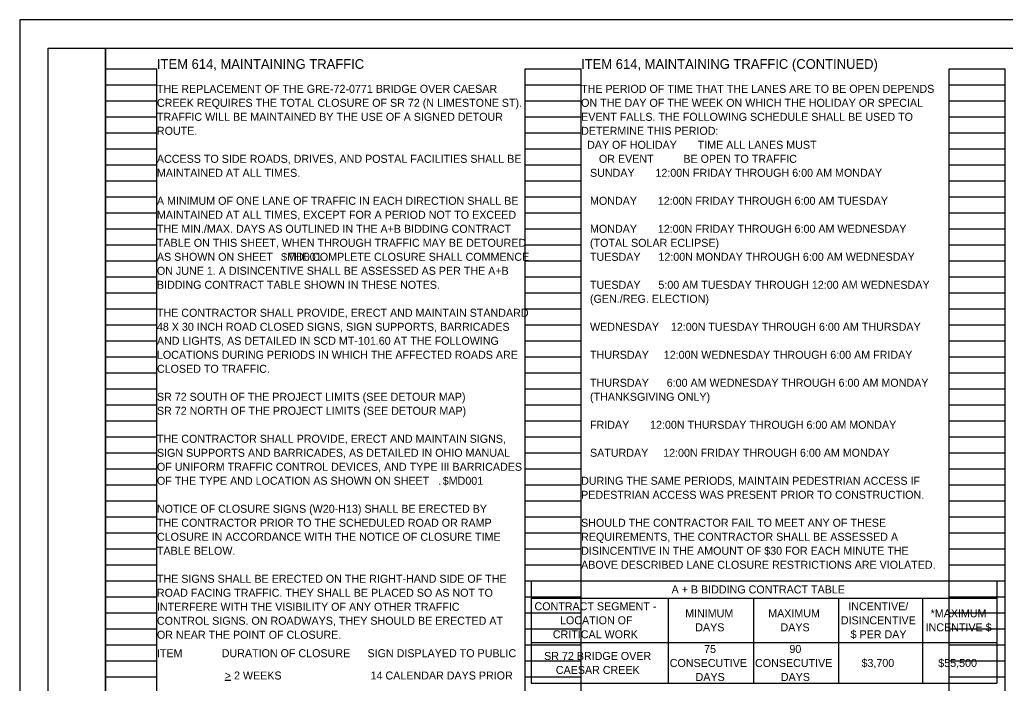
# Model space of a CAD drawing. Extents: x 0 to 69, y 0 to 22.
# Drawn here: x 0 to 17.24, y 10.39 to 22 of the extents above; entities that cross this region are included whole.
import ezdxf

# ---------------------------------------------------------------- set-up
doc = ezdxf.new("R2010")
doc.units = 0
for name, color, linetype in [('GM_X_City_Street', 7, 'Continuous'), ('GM_X_US_Route', 7, 'Continuous'), ('SH_Border', 7, 'Continuous'), ('SH_Cut_Line', 7, 'Continuous'), ('SH_Text', 7, 'Continuous')]:
    doc.layers.add(name, color=color, linetype=linetype)

msp = doc.modelspace()

# ---------------------------------------------------------------- linework, layer by layer
at = {"layer": 'GM_X_City_Street'}
for p, q in [((1.5, 0.98), (1.5, 21.14)), ((1.5, 21.14), (2.4, 21.14)), ((2.4, 0.98), (2.4, 21.14)), ((8.84, 0.98), (8.84, 21.14)), ((8.84, 21.14), (9.82, 21.14)), ((9.82, 0.98), (9.82, 21.14)), ((16.26, 0.98), (16.26, 21.14)), ((16.26, 21.14), (17.24, 21.14)), ((17.24, 0.98), (17.24, 21.14)), ((1.5, 20.86), (2.4, 20.86)), ((8.84, 20.86), (9.82, 20.86)), ((16.26, 20.86), (17.24, 20.86)), ((1.5, 20.58), (2.4, 20.58)), ((8.84, 20.58), (9.82, 20.58)), ((16.26, 20.58), (17.24, 20.58)), ((1.5, 20.3), (2.4, 20.3)), ((8.84, 20.3), (9.82, 20.3)), ((16.26, 20.3), (17.24, 20.3)), ((1.5, 20.02), (2.4, 20.02)), ((8.84, 20.02), (9.82, 20.02)), ((16.26, 20.02), (17.24, 20.02)), ((1.5, 19.74), (2.4, 19.74)), ((8.84, 19.74), (9.82, 19.74)), ((16.26, 19.74), (17.24, 19.74)), ((1.5, 19.46), (2.4, 19.46)), ((8.84, 19.46), (9.82, 19.46)), ((16.26, 19.46), (17.24, 19.46)), ((1.5, 19.18), (2.4, 19.18)), ((8.84, 19.18), (9.82, 19.18)), ((16.26, 19.18), (17.24, 19.18)), ((1.5, 18.9), (2.4, 18.9)), ((8.84, 18.9), (9.82, 18.9)), ((16.26, 18.9), (17.24, 18.9)), ((1.5, 18.62), (2.4, 18.62)), ((8.84, 18.62), (9.82, 18.62)), ((16.26, 18.62), (17.24, 18.62)), ((1.5, 18.34), (2.4, 18.34)), ((8.84, 18.34), (9.82, 18.34)), ((16.26, 18.34), (17.24, 18.34)), ((1.5, 18.06), (2.4, 18.06)), ((8.84, 18.06), (9.82, 18.06)), ((16.26, 18.06), (17.24, 18.06)), ((1.5, 17.78), (2.4, 17.78)), ((8.84, 17.78), (9.82, 17.78)), ((16.26, 17.78), (17.24, 17.78)), ((1.5, 17.5), (2.4, 17.5)), ((8.84, 17.5), (9.82, 17.5)), ((16.26, 17.5), (17.24, 17.5)), ((1.5, 17.22), (2.4, 17.22)), ((8.84, 17.22), (9.82, 17.22)), ((16.26, 17.22), (17.24, 17.22)), ((1.5, 16.94), (2.4, 16.94)), ((8.84, 16.94), (9.82, 16.94)), ((16.26, 16.94), (17.24, 16.94)), ((1.5, 16.66), (2.4, 16.66)), ((8.84, 16.66), (9.82, 16.66)), ((16.26, 16.66), (17.24, 16.66)), ((1.5, 16.38), (2.4, 16.38)), ((8.84, 16.38), (9.82, 16.38)), ((16.26, 16.38), (17.24, 16.38)), ((1.5, 16.1), (2.4, 16.1)), ((8.84, 16.1), (9.82, 16.1)), ((16.26, 16.1), (17.24, 16.1)), ((1.5, 15.82), (2.4, 15.82)), ((8.84, 15.82), (9.82, 15.82)), ((16.26, 15.82), (17.24, 15.82)), ((1.5, 15.54), (2.4, 15.54)), ((8.84, 15.54), (9.82, 15.54)), ((16.26, 15.54), (17.24, 15.54)), ((1.5, 15.26), (2.4, 15.26)), ((8.84, 15.26), (9.82, 15.26)), ((16.26, 15.26), (17.24, 15.26)), ((1.5, 14.98), (2.4, 14.98)), ((8.84, 14.98), (9.82, 14.98)), ((16.26, 14.98), (17.24, 14.98)), ((1.5, 14.7), (2.4, 14.7)), ((8.84, 14.7), (9.82, 14.7)), ((16.26, 14.7), (17.24, 14.7)), ((1.5, 14.42), (2.4, 14.42)), ((8.84, 14.42), (9.82, 14.42)), ((16.26, 14.42), (17.24, 14.42)), ((1.5, 14.14), (2.4, 14.14)), ((8.84, 14.14), (9.82, 14.14)), ((16.26, 14.14), (17.24, 14.14)), ((1.5, 13.86), (2.4, 13.86)), ((8.84, 13.86), (9.82, 13.86)), ((16.26, 13.86), (17.24, 13.86)), ((1.5, 13.58), (2.4, 13.58)), ((8.84, 13.58), (9.82, 13.58)), ((16.26, 13.58), (17.24, 13.58)), ((1.5, 13.3), (2.4, 13.3)), ((8.84, 13.3), (9.82, 13.3)), ((16.26, 13.3), (17.24, 13.3)), ((1.5, 13.02), (2.4, 13.02)), ((8.84, 13.02), (9.82, 13.02)), ((16.26, 13.02), (17.24, 13.02)), ((1.5, 12.74), (2.4, 12.74)), ((8.84, 12.74), (9.82, 12.74)), ((16.26, 12.74), (17.24, 12.74)), ((1.5, 12.46), (2.4, 12.46)), ((8.84, 12.46), (9.82, 12.46)), ((16.26, 12.46), (17.24, 12.46)), ((1.5, 12.18), (2.4, 12.18)), ((8.84, 12.18), (9.82, 12.18)), ((16.26, 12.18), (17.24, 12.18)), ((1.5, 11.9), (2.4, 11.9)), ((8.84, 11.9), (9.82, 11.9)), ((16.26, 11.9), (17.24, 11.9)), ((1.5, 11.62), (2.4, 11.62)), ((8.84, 11.62), (9.82, 11.62)), ((16.26, 11.62), (17.24, 11.62)), ((1.5, 11.34), (2.4, 11.34)), ((8.84, 11.34), (9.82, 11.34)), ((16.26, 11.34), (17.24, 11.34)), ((1.5, 11.06), (2.4, 11.06)), ((8.84, 11.06), (9.82, 11.06)), ((16.26, 11.06), (17.24, 11.06)), ((1.5, 10.78), (2.4, 10.78)), ((8.84, 10.78), (9.82, 10.78)), ((16.26, 10.78), (17.24, 10.78)), ((1.5, 10.5), (2.4, 10.5)), ((8.84, 10.5), (9.82, 10.5)), ((16.26, 10.5), (17.24, 10.5))]:
    msp.add_line(p, q, dxfattribs=at)
at = {"layer": 'GM_X_US_Route'}
for p, q in [((8.944, 12.18), (17.094, 12.18)), ((8.944, 12.18), (8.944, 10.387)), ((17.094, 12.18), (17.094, 10.387)), ((8.944, 11.876), (17.094, 11.876)), ((11.342, 11.876), (11.342, 10.387)), ((12.834, 11.876), (12.834, 10.387)), ((14.325, 11.876), (14.325, 10.387)), ((15.792, 11.876), (15.792, 10.387)), ((8.944, 11.1), (17.094, 11.1)), ((8.944, 10.387), (17.094, 10.387))]:
    msp.add_line(p, q, dxfattribs=at)
at = {"layer": 'SH_Border'}
for points in [[(0.5, 21.5), (1.5, 21.5), (1.5, 0.5), (0.5, 0.5)], [(1.5, 21.5), (33.5, 21.5), (33.5, 0.5), (1.5, 0.5)]]:
    msp.add_lwpolyline(points, close=True, dxfattribs=at)
at = {"layer": 'SH_Cut_Line'}
msp.add_lwpolyline([(0, 0), (34, 0), (34, 22), (0, 22)], close=True, dxfattribs=at)
at = {"layer": 'SH_Text'}
msp.add_line((3.591, 10.44), (3.692, 10.44), dxfattribs=at)

# ---------------------------------------------------------------- texts
at = {"layer": 'GM_X_US_Route'}
for s, p in [('A + B BIDDING CONTRACT TABLE', (11.403, 11.958)), ('CONTRACT SEGMENT - ', (9.005, 11.663)), ('INCENTIVE/', (14.493, 11.663)), ('LOCATION OF', (9.451, 11.418)), ('MINIMUM', (11.64, 11.54)), ('MAXIMUM', (13.093, 11.54)), ('DISINCENTIVE', (14.364, 11.418)), ('*MAXIMUM', (15.934, 11.54)), ('DAYS', (11.817, 11.295)), ('DAYS', (13.308, 11.295)), ('INCENTIVE $', (15.847, 11.295)), ('CRITICAL WORK', (9.326, 11.173)), ('$ PER DAY', (14.534, 11.173)), ('75', (11.972, 10.916)), ('90', (13.464, 10.916)), ('SR 72 BRIDGE OVER', (9.173, 10.794)), ('CAESAR CREEK', (9.378, 10.549)), ('CONSECUTIVE', (11.371, 10.671)), ('CONSECUTIVE', (12.863, 10.671)), ('$3,700', (14.725, 10.671)), ('$55,500', (16.068, 10.671)), ('DAYS', (11.823, 10.426)), ('DAYS', (13.314, 10.426))]:
    msp.add_text(s, height=0.14, dxfattribs=at).set_placement(p)
at = {"layer": 'SH_Text'}
for s, height, p in [('ITEM 614, MAINTAINING TRAFFIC', 0.17, (2.4, 21.14)), ('ITEM 614, MAINTAINING TRAFFIC (CONTINUED)', 0.17, (9.82, 21.14)), ('THE REPLACEMENT OF THE GRE-72-0771 BRIDGE OVER CAESAR ', 0.14, (2.4, 20.72)), ('THE PERIOD OF TIME THAT THE LANES ARE TO BE OPEN DEPENDS ', 0.14, (9.82, 20.72)), ('CREEK REQUIRES THE TOTAL CLOSURE OF SR 72 (N LIMESTONE ST). ', 0.14, (2.4, 20.475)), ('ON THE DAY OF THE WEEK ON WHICH THE HOLIDAY OR SPECIAL ', 0.14, (9.82, 20.475)), ('TRAFFIC WILL BE MAINTAINED BY THE USE OF A SIGNED DETOUR ', 0.14, (2.4, 20.23)), ('EVENT FALLS. THE FOLLOWING SCHEDULE SHALL BE USED TO ', 0.14, (9.82, 20.23)), ('ROUTE.', 0.14, (2.4, 19.985)), ('DETERMINE THIS PERIOD:', 0.14, (9.82, 19.985)), ('  DAY OF HOLIDAY       TIME ALL LANES MUST', 0.14, (9.82, 19.74)), ('ACCESS TO SIDE ROADS, DRIVES, AND POSTAL FACILITIES SHALL BE ', 0.14, (2.4, 19.495)), ('      OR EVENT          BE OPEN TO TRAFFIC', 0.14, (9.82, 19.495)), ('MAINTAINED AT ALL TIMES. ', 0.14, (2.4, 19.25)), ('   SUNDAY       12:00N FRIDAY THROUGH 6:00 AM MONDAY', 0.14, (9.82, 19.25)), ('A MINIMUM OF ONE LANE OF TRAFFIC IN EACH DIRECTION SHALL BE ', 0.14, (2.4, 18.76)), ('   MONDAY       12:00N FRIDAY THROUGH 6:00 AM TUESDAY', 0.14, (9.82, 18.76)), ('MAINTAINED AT ALL TIMES, EXCEPT FOR A PERIOD NOT TO EXCEED ', 0.14, (2.4, 18.515)), ('THE MIN./MAX. DAYS AS OUTLINED IN THE A+B BIDDING CONTRACT ', 0.14, (2.4, 18.27)), ('   MONDAY       12:00N FRIDAY THROUGH 6:00 AM WEDNESDAY', 0.14, (9.82, 18.27)), ('TABLE ON THIS SHEET, WHEN THROUGH TRAFFIC MAY BE DETOURED ', 0.14, (2.4, 18.025)), ('   (TOTAL SOLAR ECLIPSE)                      ', 0.14, (9.82, 18.025)), ('$MD001', 0.14, (4.573, 17.78)), ('AS SHOWN ON SHEET   . THE COMPLETE CLOSURE SHALL COMMENCE ', 0.14, (2.4, 17.78)), ('   TUESDAY      12:00N MONDAY THROUGH 6:00 AM WEDNESDAY', 0.14, (9.82, 17.78)), ('ON JUNE 1. A DISINCENTIVE SHALL BE ASSESSED AS PER THE A+B ', 0.14, (2.4, 17.535)), ('BIDDING CONTRACT TABLE SHOWN IN THESE NOTES.', 0.14, (2.4, 17.29)), ('   TUESDAY      5:00 AM TUESDAY THROUGH 12:00 AM WEDNESDAY                ', 0.14, (9.82, 17.29)), ('   (GEN./REG. ELECTION)', 0.14, (9.82, 17.045)), ('THE CONTRACTOR SHALL PROVIDE, ERECT AND MAINTAIN STANDARD ', 0.14, (2.4, 16.8)), ('48 X 30 INCH ROAD CLOSED SIGNS, SIGN SUPPORTS, BARRICADES ', 0.14, (2.4, 16.555)), ('   WEDNESDAY    12:00N TUESDAY THROUGH 6:00 AM THURSDAY', 0.14, (9.82, 16.555)), ('AND LIGHTS, AS DETAILED IN SCD MT-101.60 AT THE FOLLOWING ', 0.14, (2.4, 16.31)), ('LOCATIONS DURING PERIODS IN WHICH THE AFFECTED ROADS ARE ', 0.14, (2.4, 16.065)), ('   THURSDAY     12:00N WEDNESDAY THROUGH 6:00 AM FRIDAY', 0.14, (9.82, 16.065)), ('CLOSED TO TRAFFIC.', 0.14, (2.4, 15.82)), ('   THURSDAY      6:00 AM WEDNESDAY THROUGH 6:00 AM MONDAY', 0.14, (9.82, 15.575)), ('SR 72 SOUTH OF THE PROJECT LIMITS (SEE DETOUR MAP)', 0.14, (2.4, 15.33)), ('   (THANKSGIVING ONLY)', 0.14, (9.82, 15.33)), ('SR 72 NORTH OF THE PROJECT LIMITS (SEE DETOUR MAP)', 0.14, (2.4, 15.085)), ('   FRIDAY       12:00N THURSDAY THROUGH 6:00 AM MONDAY', 0.14, (9.82, 14.84)), ('THE CONTRACTOR SHALL PROVIDE, ERECT AND MAINTAIN SIGNS, ', 0.14, (2.4, 14.595)), ('SIGN SUPPORTS AND BARRICADES, AS DETAILED IN OHIO MANUAL', 0.14, (2.4, 14.35)), ('   SATURDAY     12:00N FRIDAY THROUGH 6:00 AM MONDAY', 0.14, (9.82, 14.35)), ('OF UNIFORM TRAFFIC CONTROL DEVICES, AND TYPE III BARRICADES', 0.14, (2.4, 14.105)), ('OF THE TYPE AND LOCATION AS SHOWN ON SHEET   .', 0.14, (2.4, 13.86)), ('$MD001', 0.14, (7.4, 13.86)), ('DURING THE SAME PERIODS, MAINTAIN PEDESTRIAN ACCESS IF ', 0.14, (9.82, 13.86)), ('PEDESTRIAN ACCESS WAS PRESENT PRIOR TO CONSTRUCTION.', 0.14, (9.82, 13.615)), ('NOTICE OF CLOSURE SIGNS (W20-H13) SHALL BE ERECTED BY ', 0.14, (2.4, 13.37)), ('THE CONTRACTOR PRIOR TO THE SCHEDULED ROAD OR RAMP ', 0.14, (2.4, 13.125)), ('SHOULD THE CONTRACTOR FAIL TO MEET ANY OF THESE ', 0.14, (9.82, 13.125)), ('CLOSURE IN ACCORDANCE WITH THE NOTICE OF CLOSURE TIME ', 0.14, (2.4, 12.88)), ('REQUIREMENTS, THE CONTRACTOR SHALL BE ASSESSED A ', 0.14, (9.82, 12.88)), ('TABLE BELOW.', 0.14, (2.4, 12.635)), ('DISINCENTIVE IN THE AMOUNT OF $30 FOR EACH MINUTE THE ', 0.14, (9.82, 12.635)), ('ABOVE DESCRIBED LANE CLOSURE RESTRICTIONS ARE VIOLATED.', 0.14, (9.82, 12.39)), ('THE SIGNS SHALL BE ERECTED ON THE RIGHT-HAND SIDE OF THE ', 0.14, (2.4, 12.145)), ('ROAD FACING TRAFFIC. THEY SHALL BE PLACED SO AS NOT TO ', 0.14, (2.4, 11.9)), ('INTERFERE WITH THE VISIBILITY OF ANY OTHER TRAFFIC ', 0.14, (2.4, 11.655)), ('CONTROL SIGNS. ON ROADWAYS, THEY SHOULD BE ERECTED AT ', 0.14, (2.4, 11.41)), ('OR NEAR THE POINT OF CLOSURE.', 0.14, (2.4, 11.165)), ('ITEM', 0.14, (2.4, 10.842)), ('DURATION OF CLOSURE', 0.14, (3.534, 10.842)), ('SIGN DISPLAYED TO PUBLIC', 0.14, (6.084, 10.842)), ('> 2 WEEKS', 0.14, (3.587, 10.452)), ('14 CALENDAR DAYS PRIOR ', 0.14, (6.138, 10.452))]:
    msp.add_text(s, height=height, dxfattribs=at).set_placement(p)

doc.saveas('drawing.dxf')
